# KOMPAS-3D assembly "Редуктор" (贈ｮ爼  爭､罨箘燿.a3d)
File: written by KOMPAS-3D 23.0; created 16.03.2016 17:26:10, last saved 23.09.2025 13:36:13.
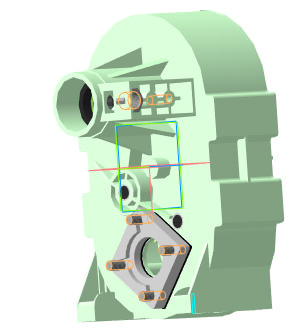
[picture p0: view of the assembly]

Document properties: Автор: Аня; Полное имя файла: C:\Users\zyrianova_ae\Desktop\Задание_колледж\Модели\Сборка редуктора.a3d

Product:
- Component [detail]: Корпус редуктора  | pos. 1  | Масса: 1.575936; Автор: Аня; source file: Корпус редуктора.m3d
- Component [detail]: Большая втулка  | pos. 2  | Масса: 0.09723; Автор: Аня; Знак неуказанной шероховатости: 1; source file: Большая втулка.m3d
- Component [detail]: Втулка  | pos. 3  | Масса: 0.003317; Автор: Аня; source file: Втулка.m3d .m3d
- Component [detail]: Втулка  | pos. 4  | Масса: 0.003317; Автор: Аня; source file: Втулка.m3d .m3d
- Component [detail]: Вал  | pos. 5  | Масса: 0.023448; Автор: Аня; source file: Вал.m3d
- Component [detail]: Вал  | pos. 6  | Масса: 0.020394; Автор: Аня; source file: Вал.m3d2.m3d
- Component [detail]: Верхняя шестеренка  | pos. 7  | Масса: 0.562638; Автор: Аня; source file: Верхняя шестеренка.m3d
- Component [detail]: Втулка  | pos. 8  | Масса: 0.014259; Автор: Аня; source file: Втулка.m3d фигурная.m3d
- Component [detail]: Шестеренка  | pos. 9  | Масса: 0.206253; Автор: Аня; source file: Шестеренка.m3d средняя.m3d
- Component [detail]: Шестерня  | pos. 10  | Масса: 0.110592; Автор: Аня; source file: Шестерня.m3d нижняя.m3d
- Component [detail]: Стопорное кольцо  | pos. 11  | Масса: 0.000276; Автор: Аня; source file: Стопорное кольцо.m3d к верхней шестеренке.m3d
- Component [detail]: Стопорное кольцо  | pos. 12  | Масса: 0.000055; Автор: Аня; source file: Стопорное кольцо.m3d
- Component [detail]: Стопорное кольцо  | pos. 13  | Масса: 0.000055; Автор: Аня; source file: Стопорное кольцо.m3d
- Component [detail]: Крышка редуктора  | pos. 14  | Масса: 0.277651; Автор: Аня; source file: Крышка редуктора.m3d
- Component [detail]: Прокладка  | pos. 15  | Масса: 0.016066; Автор: Аня; source file: Прокладка.m3d черная.m3d
- Component [detail]: Прокладка  | pos. 16  | Масса: 0.074897; Автор: Аня; source file: Прокладка.m3d серая.m3d
- Component [standard]: Гайка М10x1-6H ГОСТ 15521-70  | qty 1  | Масса: 0.006256; Раздел спецификации: Стандартные изделия; Рассекать на разрезах: no
- Component [standard]: Винт с плоской головкой ГОСТ Р ИСО 1580 - М6 x 20  | qty 4  | pos. 17  | Материал: Не определено (density 0 kg/m3); Масса: 0.00614; Раздел спецификации: Стандартные изделия; Рассекать на разрезах: no; additional columns: ГОСТ Р ИСО 1580-2013
- Part/product: Редуктор
    Масса: 3.0172

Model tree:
1. Сечение поверхностью:1
2. Плоскость через три вершины:1  (with: Вырезать элемент выдавливания:21, Операция выдавливания:22, Вырезать элемент выдавливания:8, Вырезать элемент выдавливания:12, Операция выдавливания:1, Вырезать элемент выдавливания:1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)  (labels: Фаска:4)
     Расстояние = -10

Referenced files in C:\Users\zyrianova_ae\Desktop\Задание_колледж\Модели\: Корпус редуктора.m3d, Большая втулка.m3d, Втулка.m3d .m3d, Вал.m3d, Вал.m3d2.m3d, Верхняя шестеренка.m3d, Втулка.m3d фигурная.m3d, Шестеренка.m3d средняя.m3d, Шестерня.m3d нижняя.m3d, Стопорное кольцо.m3d к верхней шестеренке.m3d, Стопорное кольцо.m3d, Крышка редуктора.m3d, Прокладка.m3d черная.m3d, Прокладка.m3d серая.m3d
Referenced files in C:\DB\SI\Methods\Kompas\3D\: PLib_Nut_OST92_900.m3d, PLib_Screw_ISO_1207_1500.m3d
Referenced files in T:\ОИТОД\Электрическая мясорубка\Электрическая мясорубка\: Втулка.m3d .m3d, Стопорное кольцо.m3d
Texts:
  Крепежное изделие ГОСТ
  BOSimple***PART:44308cef-46f0-50be-f4d8-06341951c5a9***SHORTLOC:Root±30±10±20±©{}110±10±50±140[Нет;Без покрытия;Без указания материала;-;10;1;14]
  Винт с плоской головкой
  BOSimple***PART:c15c2ad8-c145-0dad-580c-0bc79dd9d5ca***SHORTLOC:B94B_EADBB73CD05D4AB1[1;20;6;Без покрытия;-;Не требуется покрытия;Без обработки;-;Undefined]
  Втулка (1)
  Втулка (2)
  Стопорное кольцо (1)
  Стопорное кольцо (2)
  bcut1
  hole1
  hcut1
  hole2
  cut1
  Винт с плоской головкой ГОСТ Р ИСО 1580 - М6 x 20 (1)
  Винт с плоской головкой ГОСТ Р ИСО 1580 - М6 x 20 (3)
  Винт с плоской головкой ГОСТ Р ИСО 1580 - М6 x 20 (5)
  Винт с плоской головкой ГОСТ Р ИСО 1580 - М6 x 20 (7)
  Pan flat head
